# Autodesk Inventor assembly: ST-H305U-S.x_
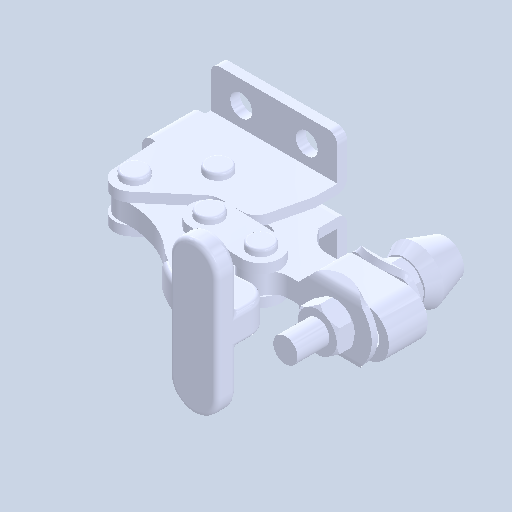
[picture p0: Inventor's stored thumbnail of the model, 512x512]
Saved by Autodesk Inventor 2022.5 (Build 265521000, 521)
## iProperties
Created: 2024-07
Part Number: ST-H305U-S.x_
Document SubType Name: Assembly
Designer: ImaoCorp
Author: ImaoCorp
Sending System: SOLIDWORKS 2022-2022290
MC: AMD64
MC_MODEL: Intel64 Family 6 Model 60 Stepping 3, GenuineIntel
OS: Windows_NT
FRU: Parasolid Version 33.1, build 260,  4-25-2022
FORMAT: text
GUISE: transmit
KEY: FILEST-H305U-S.x_t
DATE: Mon Jul 29 10:02:38 2024
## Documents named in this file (8)
- X:\14_SW2022-Inv2022\07_2024-10新製品(WHS)\OTC_データ\s\st-h305u-s\ST-H305U-S.x_.iam
- X:\14_SW2022-Inv2022\07_2024-10新製品(WHS)\OTC_データ\s\st-h305u-s\ST-H305U-S_01.ipt
- X:\14_SW2022-Inv2022\07_2024-10新製品(WHS)\OTC_データ\s\st-h305u-s\ST-H305U-S_02.ipt
- X:\14_SW2022-Inv2022\07_2024-10新製品(WHS)\OTC_データ\s\st-h305u-s\ST-H305U-S_03.ipt
- X:\14_SW2022-Inv2022\07_2024-10新製品(WHS)\OTC_データ\s\st-h305u-s\ST-H305U-S_04.ipt
- X:\14_SW2022-Inv2022\07_2024-10新製品(WHS)\OTC_データ\s\st-h305u-s\ST-H305U-S_05.ipt
- X:\14_SW2022-Inv2022\07_2024-10新製品(WHS)\OTC_データ\s\st-h305u-s\ST-H305U-S_06.ipt
- X:\14_SW2022-Inv2022\07_2024-10新製品(WHS)\OTC_データ\s\st-h305u-s\ST-H305U-S_07.ipt
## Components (7 placed, 7 different names)
1. ST-H305U-S_01
2. ST-H305U-S_02
3. ST-H305U-S_03
4. ST-H305U-S_04
5. ST-H305U-S_05
6. ST-H305U-S_06
7. ST-H305U-S_07
